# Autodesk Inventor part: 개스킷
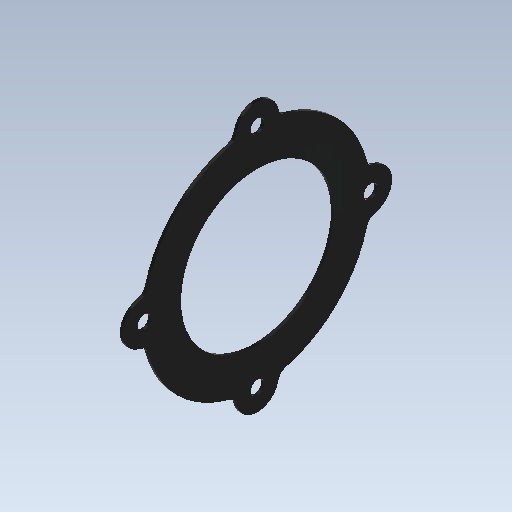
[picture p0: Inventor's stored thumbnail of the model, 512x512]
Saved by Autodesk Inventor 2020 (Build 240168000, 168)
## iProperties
Created: 2022-07
Part Number: 개스킷
Material: 황동, 연질 노란색
Document SubType Name: Modeling
Designer: mdu-01
Density: 1 g/cm^3
Appearance: 매끄러움 - 검은색
Author: mdu-01
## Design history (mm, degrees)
sketch "스케치1"
  geometry: C1 r 25 at (0, 0); C2 r 2.25 at (0, 37); C3 r 2.25 at (-37, 0); C4 r 2.25 at (0, -37); C5 r 2.25 at (37, 0); A1 r 7 centre (0, 37) between (6.969, 36.338) and (-6.969, 36.338); A2 r 7 centre (-37, 0) between (-36.338, 6.969) and (-36.338, -6.969); A3 r 7 centre (0, -37) between (-6.969, -36.338) and (6.969, -36.338); A4 r 7 centre (37, 0) between (36.338, -6.969) and (36.338, 6.969); A5 r 37 centre (0, 0) between (36.338, 6.969) and (6.969, 36.338); A6 r 37 centre (0, 0) between (-6.969, 36.338) and (-36.338, 6.969); A7 r 37 centre (0, 0) between (-36.338, -6.969) and (-6.969, -36.338); A8 r 37 centre (0, 0) between (6.969, -36.338) and (36.338, -6.969); 1 further point
  constraints: 17 point on circle, 13 centre point, 3 coincident, 1 vertical alignment, 26 other
  dimensions: "d4" = 14 diameter of A1; "d7" = 360 deg dimension on point (0, 0) A1.centre (derived); "d9" = 37 radius of A5; "d10" = 50 diameter of C1; "d13" = 4.5 diameter of C2; "d16" = 360 deg dimension on point (0, 0) C2.centre (derived)
extrude "돌출2" new body sketch "스케치1" stored distance "d18" = 1; taper "d19" = 0 deg
fillet "모깎기1" dims "d20" = 3
node "솔리드2"
other parameters: "d0" = 74
